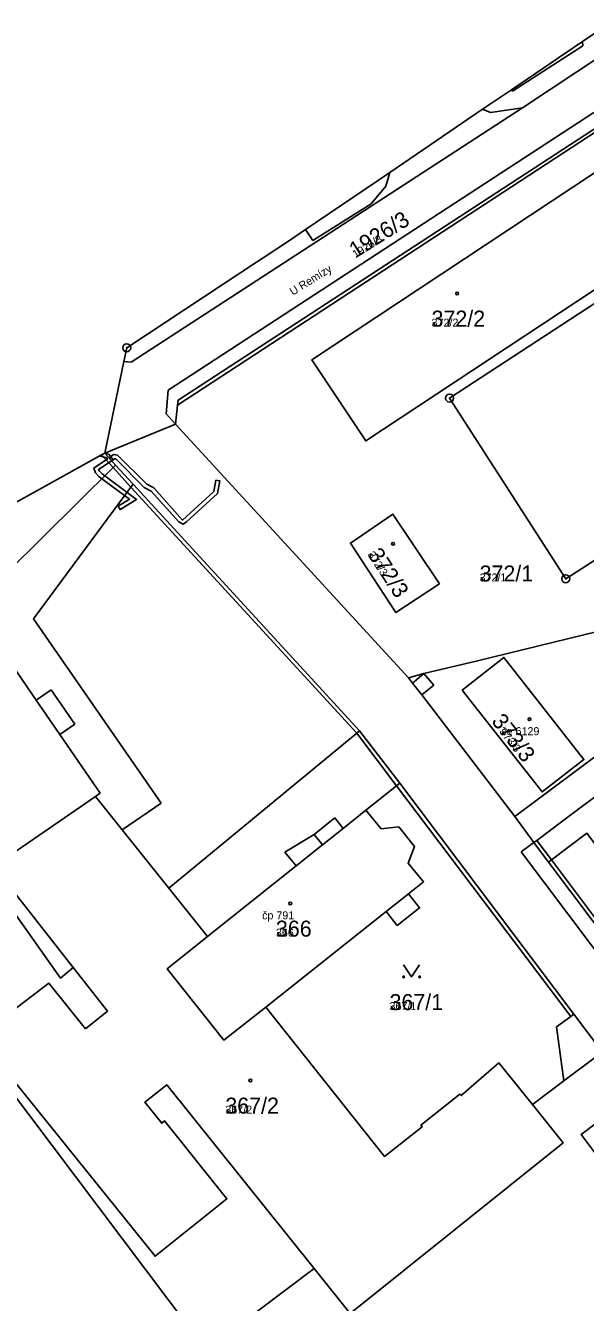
# Model space of a CAD drawing. Extents: x -763628 to -761565, y -976033 to -973833.
# Drawn here: x -762592 to -762522, y -974115.1 to -973955.5 of the extents above; entities that cross this region are included whole.
import ezdxf

# ---------------------------------------------------------------- set-up
doc = ezdxf.new("R2010")
doc.units = 0
for name, color, linetype in [('KN_cisla parcel 1000', 7, 'Continuous'), ('KN_cisla parcel 500', 7, 'Continuous'), ('KN_cisla popisna 500', 7, 'Continuous'), ('KN_hranice parcel', 7, 'Continuous'), ('KN_hranice uzemi', 7, 'Continuous'), ('KN_popisy', 7, 'Continuous'), ('KN_vecna bremena', 7, 'Continuous'), ('KN_vnitrni kresba parcel', 7, 'Continuous'), ('KN_znacky bodu BP', 7, 'Continuous'), ('KN_znacky budov', 7, 'Continuous'), ('KN_znacky kultur', 7, 'Continuous')]:
    doc.layers.add(name, color=color, linetype=linetype)

msp = doc.modelspace()

# ---------------------------------------------------------------- linework, layer by layer
at = {"layer": 'KN_hranice parcel'}
for p, q in [((-762582.07, -974008.96), (-762573.22, -974005.35)), ((-762573.22, -974005.35), (-762544.12, -974037.04)), ((-762580.7, -974010.45), (-762582.07, -974008.96)), ((-762545.21, -974050.21), (-762550.26, -974043.65)), ((-762530.85, -974054.37), (-762528.47, -974057.63)), ((-762528.47, -974057.63), (-762526.64, -974060.07)), ((-762526.64, -974060.07), (-762516.48, -974073.61)), ((-762569.4, -974121.02), (-762594.46, -974087.76)), ((-762555.9, -974110.87), (-762569.4, -974121.02))]:
    msp.add_line(p, q, dxfattribs=at)
for points in [[(-762511.01, -973966.6), (-762517.44, -973966.18), (-762572.89, -974002.33), (-762572.96, -974002.96), (-762573.22, -974005.35)], [(-762514.14, -973984.08), (-762549.47, -974007.44), (-762556.19, -973997.28), (-762520.87, -973973.91), (-762514.14, -973984.08)], [(-762510.92, -973983.75), (-762504.37, -973993.62), (-762503.96, -973994.24), (-762502.65, -973996.22), (-762502.24, -973996.89), (-762496.05, -974006.33), (-762524.48, -974024.66), (-762539, -974002.09), (-762510.92, -973983.75)], [(-762580.7, -974010.45), (-762581.02, -974010.76), (-762598.64, -974028.17), (-762612.8, -974038.75)], [(-762550.26, -974043.65), (-762578.52, -974012.84), (-762580.7, -974010.45)], [(-762540.23, -974025.28), (-762545.69, -974028.87), (-762551.37, -974020.21), (-762546.07, -974016.6), (-762540.23, -974025.28)], [(-762544.12, -974037.04), (-762542.19, -974036.51), (-762535.51, -974034.94), (-762503.49, -974027.07)], [(-762530.85, -974054.37), (-762500.7, -974031.86), (-762503.49, -974027.07)], [(-762537.42, -974038.57), (-762532.2, -974034.5), (-762522.21, -974047.27), (-762527.44, -974051.3), (-762537.42, -974038.57)], [(-762544.12, -974037.04), (-762543.61, -974037.7), (-762542.47, -974039.15), (-762530.85, -974054.37)], [(-762585.99, -974073.25), (-762587.61, -974074.56), (-762593.87, -974065.66), (-762612.8, -974038.75)], [(-762550.26, -974043.65), (-762550.59, -974043.96), (-762574.05, -974063.34)], [(-762512.41, -974045.61), (-762514.26, -974046.99), (-762524.85, -974054.93), (-762528.1, -974057.37), (-762528.47, -974057.63)], [(-762526.64, -974060.07), (-762526.28, -974059.8), (-762521.83, -974056.47), (-762516.68, -974063.34), (-762507.27, -974056.62), (-762506.89, -974057.13), (-762503.92, -974054.9), (-762507.33, -974050.37), (-762508.39, -974051.17), (-762511.36, -974047.07), (-762512.41, -974045.61)], [(-762561.95, -974078.19), (-762546.9, -974066.24), (-762545.52, -974067.98), (-762542.73, -974065.79), (-762544.12, -974064.03), (-762542.24, -974062.53), (-762544.18, -974060.2), (-762543.38, -974058.12), (-762545.33, -974055.67), (-762547.52, -974055.91), (-762549.44, -974053.6), (-762545.62, -974050.54), (-762545.21, -974050.21)], [(-762519.91, -974083.81), (-762523.46, -974079.09), (-762545.21, -974050.21)], [(-762574.05, -974063.34), (-762579.88, -974056.05), (-762583.21, -974051.88), (-762594.15, -974059.42), (-762593.64, -974060.16), (-762595.36, -974061.35), (-762585.99, -974073.25)], [(-762574.05, -974063.34), (-762569.22, -974069.39), (-762574.27, -974073.43), (-762567.17, -974082.33), (-762561.95, -974078.19)], [(-762585.99, -974073.25), (-762581.7, -974078.69), (-762584.46, -974080.9), (-762589.03, -974075.2), (-762592.93, -974078.16)], [(-762592.93, -974078.16), (-762597.69, -974082.14), (-762575.78, -974109.33), (-762566.81, -974102.14), (-762574.59, -974092.43), (-762574.95, -974092.71), (-762577.04, -974090.09), (-762574.31, -974087.9), (-762555.9, -974110.87)], [(-762561.95, -974078.19), (-762547.11, -974096.86), (-762542.43, -974093.14), (-762542.58, -974092.94), (-762537.7, -974089.06), (-762537.54, -974089.26), (-762532.82, -974085.18), (-762528.64, -974090.38)], [(-762528.64, -974090.38), (-762524.71, -974087.42), (-762520.6, -974084.33), (-762519.91, -974083.81)], [(-762515.92, -974089.13), (-762516.58, -974089.62), (-762522.56, -974094.12), (-762514.93, -974104.27), (-762508.89, -974099.74), (-762508.29, -974099.29)], [(-762555.9, -974110.87), (-762551.42, -974116.47), (-762524.81, -974095.14), (-762528.64, -974090.38)]]:
    msp.add_lwpolyline(points, dxfattribs=at)
at = {"layer": 'KN_hranice uzemi'}
for p, q in [((-762522.38, -973957.51), (-762519.44, -973955.52)), ((-762546.47, -973973.88), (-762534.86, -973965.99)), ((-762556.98, -973981.02), (-762546.47, -973973.88)), ((-762579.32, -973995.8), (-762567.27, -973987.85)), ((-762582.47, -974009.18), (-762582.07, -974008.96))]:
    msp.add_line(p, q, dxfattribs=at)
for points in [[(-762534.86, -973965.99), (-762531.26, -973963.54), (-762522.38, -973957.51)], [(-762562.27, -973984.55), (-762558.98, -973982.38), (-762556.98, -973981.02)], [(-762567.27, -973987.85), (-762563.12, -973985.11), (-762562.27, -973984.55)], [(-762582.07, -974008.96), (-762579.68, -973997.51), (-762579.32, -973995.8)], [(-762642.14, -974041.8), (-762619.19, -974029.57), (-762582.47, -974009.18)]]:
    msp.add_lwpolyline(points, dxfattribs=at)
at = {"layer": 'KN_vecna bremena'}
for points in [[(-762582.74, -974009.33), (-762581.85, -974009.52), (-762581.74, -974009.68), (-762583.41, -974010.82), (-762583.22, -974011.43), (-762582.74, -974011.94), (-762578.99, -974014.73), (-762580.4, -974015.6), (-762580.14, -974016.02), (-762578.09, -974014.77), (-762582.4, -974011.56), (-762582.78, -974011.17), (-762582.83, -974011.02), (-762581.02, -974009.8), (-762581.56, -974009.07), (-762582.07, -974008.96), (-762582.47, -974009.18)], [(-762568.17, -974012.35), (-762568.44, -974013.76), (-762572.35, -974017.33), (-762575.94, -974013.31), (-762576.82, -974012.86), (-762580.45, -974009.2), (-762580.99, -974009.14), (-762581.52, -974009.56), (-762581.18, -974009.93), (-762580.84, -974009.66), (-762580.69, -974009.68), (-762577.12, -974013.26), (-762576.25, -974013.71), (-762572.82, -974017.55), (-762572.25, -974017.84), (-762571.86, -974017.56), (-762567.98, -974014.02), (-762567.68, -974012.44)]]:
    msp.add_lwpolyline(points, close=True, dxfattribs=at)
at = {"layer": 'KN_vnitrni kresba parcel'}
for p, q in [((-762522.38, -973957.51), (-762522.36, -973958.06)), ((-762522.36, -973958.06), (-762531.13, -973963.74)), ((-762519.62, -973959.02), (-762529.88, -973965.79)), ((-762531.26, -973963.54), (-762531.13, -973963.74)), ((-762578.75, -973997.6), (-762529.88, -973965.79)), ((-762520.96, -973966.39), (-762574.15, -974001.1)), ((-762517.39, -973966.59), (-762572.96, -974002.96)), ((-762533.89, -973966.37), (-762534.86, -973965.99)), ((-762529.88, -973965.79), (-762533.89, -973966.37)), ((-762546.97, -973975.58), (-762546.47, -973973.88)), ((-762548.8, -973977.82), (-762546.97, -973975.58)), ((-762548.8, -973977.82), (-762556.09, -973982.37)), ((-762556.09, -973982.37), (-762556.98, -973981.02)), ((-762578.75, -973997.6), (-762579.68, -973997.51)), ((-762574.15, -974001.1), (-762574.41, -974004.04)), ((-762574.41, -974004.04), (-762573.22, -974005.35)), ((-762581.02, -974010.76), (-762582.47, -974009.18)), ((-762578.79, -974013.2), (-762581.02, -974010.76)), ((-762578.79, -974013.2), (-762590.98, -974029.65)), ((-762578.52, -974012.84), (-762578.79, -974013.2)), ((-762550.59, -974043.96), (-762578.79, -974013.2)), ((-762575.03, -974052.72), (-762590.98, -974029.65)), ((-762595.49, -974032.75), (-762590.63, -974039.82)), ((-762542.19, -974036.51), (-762543.61, -974037.7)), ((-762540.94, -974037.97), (-762542.19, -974036.51)), ((-762588.77, -974038.55), (-762590.63, -974039.82)), ((-762585.81, -974042.84), (-762588.77, -974038.55)), ((-762542.47, -974039.15), (-762540.94, -974037.97)), ((-762587.67, -974044.12), (-762590.63, -974039.82)), ((-762587.67, -974044.12), (-762585.81, -974042.84)), ((-762582.62, -974051.47), (-762587.67, -974044.12)), ((-762550.59, -974043.96), (-762545.62, -974050.54)), ((-762583.21, -974051.88), (-762582.62, -974051.47)), ((-762545.62, -974050.54), (-762523.84, -974079.37)), ((-762575.03, -974052.72), (-762579.88, -974056.05)), ((-762555.92, -974056.61), (-762553.33, -974054.54)), ((-762553.33, -974054.54), (-762552.27, -974055.86)), ((-762552.27, -974055.86), (-762549.44, -974053.6)), ((-762559.56, -974058.82), (-762555.92, -974056.61)), ((-762554.87, -974057.93), (-762555.92, -974056.61)), ((-762552.27, -974055.86), (-762554.87, -974057.93)), ((-762554.87, -974057.93), (-762558.16, -974060.56)), ((-762530.06, -974058.8), (-762528.47, -974057.63)), ((-762526.28, -974059.8), (-762528.1, -974057.37)), ((-762558.16, -974060.56), (-762559.56, -974058.82)), ((-762506.01, -974090.75), (-762530.06, -974058.8)), ((-762516.12, -974073.34), (-762526.28, -974059.8)), ((-762569.22, -974069.39), (-762558.16, -974060.56)), ((-762546.9, -974066.24), (-762544.12, -974064.03)), ((-762525.65, -974080.68), (-762523.84, -974079.37)), ((-762523.84, -974079.37), (-762523.46, -974079.09)), ((-762524.71, -974087.42), (-762525.65, -974080.68))]:
    msp.add_line(p, q, dxfattribs=at)
at = {"layer": 'KN_znacky bodu BP'}
for centre, radius in [((-762579.32, -973995.8), 0.5), ((-762579.32, -973995.8), 0.0303), ((-762539, -974002.09), 0.5), ((-762539, -974002.09), 0.0303), ((-762524.48, -974024.66), 0.5), ((-762524.48, -974024.66), 0.0303)]:
    msp.add_circle(centre, radius, dxfattribs=at)
at = {"layer": 'KN_znacky budov'}
for centre in [(-762538.05, -973989), (-762546.05, -974020.3), (-762529.01, -974042.22), (-762558.89, -974065.24), (-762563.87, -974087.36)]:
    msp.add_circle(centre, 0.175, dxfattribs=at)
at = {"layer": 'KN_znacky kultur'}
msp.add_lwpolyline([(-762544.73, -974072.92), (-762543.73, -974074.42), (-762542.73, -974072.92)], dxfattribs=at)
for centre in [(-762544.73, -974074.42), (-762542.73, -974074.42)]:
    msp.add_circle(centre, 0.1, dxfattribs=at)

# ---------------------------------------------------------------- texts
at = {"layer": 'KN_cisla parcel 1000'}
for s, rotation, p in [('1926/3', 32, (-762550.74, -973984.63)), ('372/3', 303, (-762549.29, -974021.62)), ('373/3', 308, (-762533.84, -974042.5))]:
    msp.add_text(s, height=2, rotation=rotation, dxfattribs=at).set_placement(p)
for s, p in [('372/2', (-762541.24, -973993.15)), ('372/1', (-762535.24, -974025)), ('366', (-762560.68, -974069.39)), ('367/1', (-762546.49, -974078.57)), ('367/2', (-762567, -974091.51))]:
    msp.add_text(s, height=2, dxfattribs=at).set_placement(p)
at = {"layer": 'KN_cisla parcel 500'}
for s, rotation, p in [('1926/3', 32, (-762550.74, -973984.63)), ('372/3', 303, (-762549.29, -974021.62)), ('373/3', 308, (-762532.83, -974043.8))]:
    msp.add_text(s, height=1, rotation=rotation, dxfattribs=at).set_placement(p)
for s, p in [('372/2', (-762541.24, -973993.15)), ('372/1', (-762535.24, -974025)), ('366', (-762560.68, -974069.39)), ('367/1', (-762546.49, -974078.57)), ('367/2', (-762567, -974091.51))]:
    msp.add_text(s, height=1, dxfattribs=at).set_placement(p)
at = {"layer": 'KN_cisla popisna 500'}
for s, p in [('če 6129', (-762532.53, -974044.21)), ('čp 791', (-762562.41, -974067.23))]:
    msp.add_text(s, height=1, dxfattribs=at).set_placement(p)
at = {"layer": 'KN_popisy'}
msp.add_text('U Remízy', height=1, rotation=32, dxfattribs=at).set_placement((-762558.57, -973989.3))

doc.saveas('drawing.dxf')
